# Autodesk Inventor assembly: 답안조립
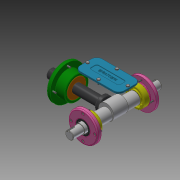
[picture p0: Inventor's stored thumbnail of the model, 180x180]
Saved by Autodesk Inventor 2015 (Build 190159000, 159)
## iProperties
Created: 2021-11
Part Number: 답안조립
Document SubType Name: Assembly
Designer: 1019876
Author: 1019876
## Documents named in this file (14)
- C:\Users\1019876\Desktop\711106V1015\답안조립.iam
- C:\Users\1019876\Desktop\711106V1015\베어링 6205.ipt
- 베어링 6205.ipt
- C:\Users\1019876\Desktop\711106V1015\본체.ipt
- C:\Users\1019876\Desktop\711106V1015\볼트 M4x0.7.ipt
- C:\Users\1019876\Desktop\711106V1015\부시.ipt
- C:\Users\1019876\Desktop\711106V1015\상부커버.ipt
- C:\Users\1019876\Desktop\711106V1015\슬라이드 커버.ipt
- C:\Users\1019876\Desktop\711106V1015\슬라이드.ipt
- C:\Users\1019876\Desktop\711106V1015\오일실.ipt
- 오일실.ipt
- C:\Users\1019876\Desktop\711106V1015\육각머리볼트 M4.ipt
- C:\Users\1019876\Desktop\711106V1015\축 커버.ipt
- C:\Users\1019876\Desktop\711106V1015\편심축.ipt
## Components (12 placed, 1 different names)
1. M4x0.7:5
2. M4x0.7:6
3. M4x0.7:7
4. M4x0.7:8
5. M4x0.7:1
6. M4x0.7:2
7. M4x0.7:3
8. M4x0.7:4
9. M4x0.7:9
10. M4x0.7:10
11. M4x0.7:11
12. M4x0.7:12
